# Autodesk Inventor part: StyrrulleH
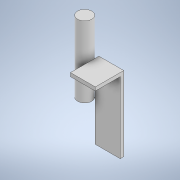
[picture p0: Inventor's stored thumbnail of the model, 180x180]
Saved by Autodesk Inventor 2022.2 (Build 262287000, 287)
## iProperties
Created: 2022-03
Part Number: StyrrulleH
Material: Generic
Document SubType Name: Modeling
Designer: cl
Density: 1 g/cm^3
Appearance: Default
Author: cl
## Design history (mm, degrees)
sketch "Sketch1"
  geometry: L1 (0, 0)-(0, -5); L2 (0, -5)-(105, -5); L3 (105, -5)-(105, 35); L4 (105, 35)-(100, 35); L5 (100, 35)-(100, 0); L6 (100, 0)-(0, 0)
  constraints: 12 end point, 5 perpendicular, 1 vertical
  dimensions: "d0" = 5 distance of L1.start L1.end; "d1" = 5 distance between parallel lines of L3 L5; "d2" = 105 distance of L1.end L2.end; "d3" = 40 distance of L2.end L3.end
extrude "Extrusion1" new body sketch "Sketch1" distance "d4" = 35; taper "d5" = 0 deg
sketch "Sketch2"
  geometry: L1 (0, 40)-(0, 0) reference; L2 (0, 0)-(35, 0) reference; L3 (35, 40)-(35, 0) reference; L4 (0, 40)-(35, 40) reference; C1 r 10 at (-10, 30); 1 further point
  constraints: 2 tangent, 1 centre point
  dimensions: "d6" = 20 diameter of C1
extrude "Extrusion2" join sketch "Sketch2" distance "d7" = 50; taper "d9" = 0 deg; dims "d8" = 50, "d10" = 0
body "Solid1"
node "Projected Loop1"
